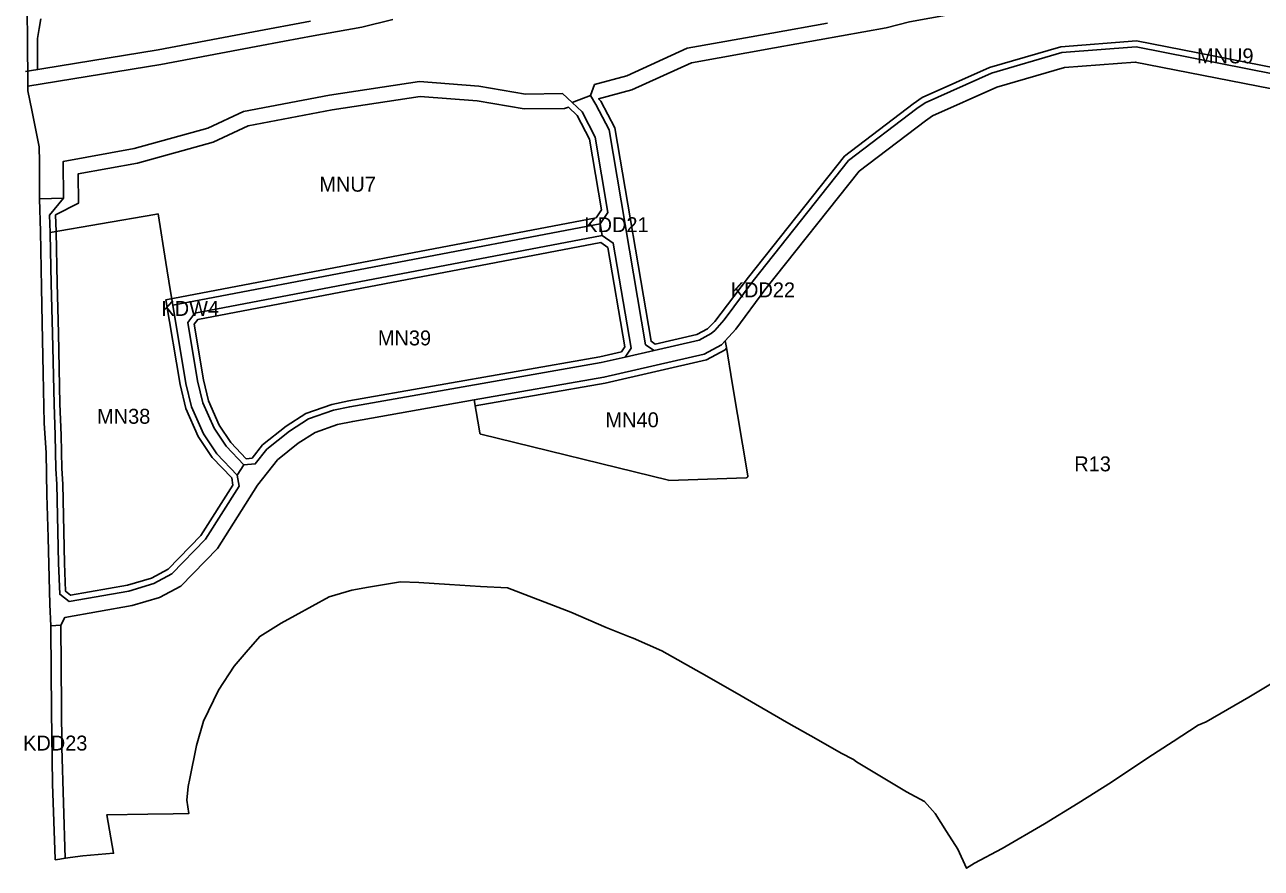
# Model space of a CAD drawing. Extents: x 7440055 to 7442242, y 5549003 to 5552256.
# Drawn here: x 7440576 to 7441405, y 5549003 to 5549569 of the extents above; entities that cross this region are included whole.
import ezdxf

# ---------------------------------------------------------------- set-up
doc = ezdxf.new("R2010")
doc.units = 0
for name, color, linetype in [('linie_rozgraniczajace', 7, 'Continuous'), ('linie_zabudowy_nieprzekraczalne', 7, 'Continuous'), ('oznaczenia_przeznaczen', 7, 'Continuous')]:
    doc.layers.add(name, color=color, linetype=linetype)

msp = doc.modelspace()

# ---------------------------------------------------------------- linework, layer by layer
at = {"layer": 'linie_rozgraniczajace'}
for points in [[(7440823.23, 5549572.15), (7440802.48, 5549567), (7440786.12, 5549564.03), (7440769.77, 5549561.06), (7440750.65, 5549557.49), (7440731.53, 5549553.91), (7440667.61, 5549541.98), (7440578.55, 5549527.43), (7440578.2, 5549559.87), (7440577.85, 5549593.22)], [(7440578.58, 5549524.38), (7440578.55, 5549527.43), (7440667.61, 5549541.98), (7440731.53, 5549553.91), (7440750.65, 5549557.49), (7440769.77, 5549561.06), (7440786.12, 5549564.03), (7440802.48, 5549567), (7440823.23, 5549572.15)], [(7441114.4, 5549569.57), (7441077.17, 5549562.92), (7441020.41, 5549552.79), (7440979.92, 5549534.41), (7440958.38, 5549528.46), (7440955.75, 5549521.17), (7440943.39, 5549516.35), (7440936.84, 5549522.52), (7440912.04, 5549522.13), (7440880.89, 5549527.4), (7440841.05, 5549530.47), (7440780.78, 5549521.32), (7440723.17, 5549510.39), (7440699.18, 5549499.3), (7440649.84, 5549485.56), (7440602.3, 5549477.01), (7440602.41, 5549452.42), (7440586.41, 5549451.77), (7440586.41, 5549452.15), (7440586.23, 5549476.79), (7440586.16, 5549486.75), (7440581.21, 5549511.31), (7440578.58, 5549524.38)], [(7441414.05, 5549535.54), (7441321.31, 5549553.68), (7441271.56, 5549549.88), (7441224.51, 5549536.13), (7441179.99, 5549516.21), (7441174.35, 5549512.4), (7441128.65, 5549477.58), (7441064.64, 5549396.93), (7441045.31, 5549370.83), (7441038.88, 5549363.69), (7441036.62, 5549361.59), (7441028.38, 5549357.15), (7440998.31, 5549350.27), (7440992.6, 5549354.08), (7440968.05, 5549498.13), (7440959.27, 5549515.02), (7440955.75, 5549521.17), (7440958.38, 5549528.46), (7440979.92, 5549534.41), (7441020.41, 5549552.79), (7441077.17, 5549562.92), (7441114.4, 5549569.57)], [(7440593.91, 5549165.7), (7440593.36, 5549179.81), (7440592.06, 5549224.79), (7440591.7, 5549239.14), (7440591.33, 5549253.49), (7440591.06, 5549267.54), (7440590.78, 5549281.6), (7440589.56, 5549301.44), (7440588.89, 5549335.09), (7440588.23, 5549368.74), (7440587.71, 5549392.53), (7440586.9, 5549430), (7440586.41, 5549451.77), (7440602.41, 5549452.42), (7440593.08, 5549441.02), (7440593.45, 5549429.24), (7440593.47, 5549428.4), (7440594.19, 5549395.2), (7440595.06, 5549361.81), (7440596.06, 5549314.32), (7440596.91, 5549293.42), (7440597.35, 5549270.93), (7440598, 5549260.51), (7440599.16, 5549207.58), (7440599.88, 5549186.82), (7440606.11, 5549181.86), (7440646.21, 5549188.94), (7440662.94, 5549193.9), (7440674.98, 5549200.38), (7440697.67, 5549223.68), (7440720.11, 5549259.17), (7440718.91, 5549266.62), (7440723.24, 5549273.46), (7440730.91, 5549274.17), (7440738.73, 5549284.11), (7440753.99, 5549296.19), (7440766.6, 5549304.29), (7440783.3, 5549310.15), (7440794.33, 5549312.51), (7440962.71, 5549342.13), (7440978.8, 5549345.81), (7440998.31, 5549350.27), (7441028.38, 5549357.15), (7441036.62, 5549361.59), (7441038.88, 5549363.69), (7441045.31, 5549370.83), (7441064.64, 5549396.93), (7441128.65, 5549477.58), (7441174.35, 5549512.4), (7441179.99, 5549516.21), (7441224.51, 5549536.13), (7441271.56, 5549549.88), (7441321.31, 5549553.68), (7441414.05, 5549535.54)], [(7440603.54, 5549009.75), (7440601.38, 5549083.97), (7440600.53, 5549165.95), (7440603.41, 5549171.23), (7440648.5, 5549179.19), (7440666.77, 5549184.6), (7440681.07, 5549192.3), (7440705.56, 5549217.46), (7440718.99, 5549238.69), (7440732.42, 5549259.91), (7440745.86, 5549277.01), (7440759.81, 5549288.04), (7440771.02, 5549295.24), (7440786.01, 5549300.51), (7440796.24, 5549302.69), (7440877.73, 5549317.03), (7440881.43, 5549294.9), (7440881.44, 5549294.84), (7440881.46, 5549294.78), (7440881.48, 5549294.72), (7440881.5, 5549294.66), (7440881.53, 5549294.6), (7440881.56, 5549294.55), (7440881.59, 5549294.5), (7440881.63, 5549294.44), (7440881.67, 5549294.4), (7440881.72, 5549294.35), (7440881.76, 5549294.31), (7440881.81, 5549294.27), (7440881.86, 5549294.23), (7440881.92, 5549294.2), (7440881.97, 5549294.17), (7440882.03, 5549294.14), (7440882.09, 5549294.12), (7440882.15, 5549294.1), (7440882.18, 5549294.1), (7441007.96, 5549263.17), (7441008.02, 5549263.16), (7441008.08, 5549263.15), (7441008.14, 5549263.15), (7441008.21, 5549263.15), (7441008.23, 5549263.15), (7441060.08, 5549264.92), (7441060.14, 5549264.92), (7441060.2, 5549264.93), (7441060.27, 5549264.94), (7441060.33, 5549264.96), (7441060.39, 5549264.98), (7441060.45, 5549265), (7441060.5, 5549265.03), (7441060.56, 5549265.06), (7441060.61, 5549265.09), (7441060.66, 5549265.13), (7441060.71, 5549265.17), (7441060.76, 5549265.22), (7441060.8, 5549265.26), (7441060.84, 5549265.31), (7441060.88, 5549265.36), (7441060.91, 5549265.42), (7441060.94, 5549265.47), (7441060.97, 5549265.53), (7441060.99, 5549265.59), (7441061.01, 5549265.65), (7441061.02, 5549265.71), (7441061.03, 5549265.77), (7441061.04, 5549265.84), (7441061.04, 5549265.9), (7441061.04, 5549265.96), (7441061.04, 5549266.02), (7441061.03, 5549266.08), (7441050.67, 5549328.58), (7441046.74, 5549352.29), (7441046.01, 5549356.67), (7441053.06, 5549364.49), (7441072.57, 5549390.85), (7441135.7, 5549470.38), (7441180.19, 5549504.27), (7441184.87, 5549507.44), (7441227.98, 5549526.72), (7441273.36, 5549539.99), (7441320.72, 5549543.6), (7441411.29, 5549525.89)], [(7441411.29, 5549525.89), (7441320.72, 5549543.6), (7441273.36, 5549539.99), (7441227.98, 5549526.72), (7441184.87, 5549507.44), (7441180.19, 5549504.27), (7441135.7, 5549470.38), (7441072.57, 5549390.85), (7441053.06, 5549364.49), (7441046.01, 5549356.67), (7441043.43, 5549353.9), (7441031.93, 5549347.7), (7440964.69, 5549332.32), (7440877.73, 5549317.03), (7440796.24, 5549302.69), (7440786.01, 5549300.51), (7440771.02, 5549295.24), (7440759.81, 5549288.04), (7440745.86, 5549277.01), (7440732.42, 5549259.91), (7440718.99, 5549238.69), (7440705.56, 5549217.46), (7440681.07, 5549192.3), (7440666.77, 5549184.6), (7440648.5, 5549179.19), (7440603.41, 5549171.23)], [(7440966.2, 5549164.55), (7440942.43, 5549174.75), (7440899.99, 5549191.07), (7440881.94, 5549192.02), (7440861.22, 5549193.3), (7440840.5, 5549194.59), (7440828.26, 5549195.02), (7440806.96, 5549191.62), (7440795.74, 5549189.49), (7440780.52, 5549185.1), (7440757.75, 5549172.48), (7440748.36, 5549167.43), (7440733.98, 5549158.49), (7440724.9, 5549147.91), (7440716.86, 5549138.54), (7440706.22, 5549122.47), (7440696.18, 5549101.65), (7440691.59, 5549085.4), (7440687.12, 5549063.29), (7440685.99, 5549057.83), (7440685.12, 5549048.67), (7440686.34, 5549039.72), (7440675.84, 5549039.58), (7440659.01, 5549039.36), (7440631.57, 5549039), (7440636.03, 5549013.17), (7440615.28, 5549011.38), (7440603.54, 5549009.75)], [(7440603.41, 5549171.23), (7440600.53, 5549165.95), (7440593.91, 5549165.7)], [(7441424.45, 5549134.26), (7441396.95, 5549117.87), (7441368.31, 5549101.16), (7441363.01, 5549099.01), (7441346.08, 5549088.12), (7441329.15, 5549077.22), (7441304.81, 5549060.8), (7441282.6, 5549046.8), (7441259.95, 5549032.95), (7441231.66, 5549016.33), (7441213.11, 5549006.49), (7441207.73, 5549003.08), (7441201.94, 5549015.9), (7441194.27, 5549027.84), (7441186.6, 5549039.78), (7441179.56, 5549047.79), (7441167.51, 5549054.39), (7441134.02, 5549074.36), (7441131.82, 5549076.1), (7441123.61, 5549080.33), (7441106.91, 5549089.91), (7441088.61, 5549100.12), (7441052.45, 5549121.05), (7441030.11, 5549133.93), (7441003.5, 5549148.84), (7440984.2, 5549157.37), (7440981.79, 5549158.34), (7440966.2, 5549164.55)]]:
    msp.add_lwpolyline(points, dxfattribs=at)
for points in [[(7440593.45, 5549429.24), (7440593.08, 5549441.02), (7440602.41, 5549452.42), (7440602.3, 5549477.01), (7440649.84, 5549485.56), (7440699.18, 5549499.3), (7440723.17, 5549510.39), (7440780.78, 5549521.32), (7440841.05, 5549530.47), (7440880.89, 5549527.4), (7440912.04, 5549522.13), (7440936.84, 5549522.52), (7440943.39, 5549516.35), (7440949.95, 5549510.18), (7440958.73, 5549493.28), (7440967.33, 5549442.8), (7440962.1, 5549435.18), (7440675.74, 5549380.5), (7440674, 5549390.99), (7440670.95, 5549409.16), (7440665.84, 5549441.75), (7440663.63, 5549441.37), (7440627.13, 5549435.07)], [(7440943.39, 5549516.35), (7440955.75, 5549521.17), (7440959.27, 5549515.02), (7440968.05, 5549498.13), (7440992.6, 5549354.08), (7440998.31, 5549350.27), (7440978.8, 5549345.81), (7440982.83, 5549351.85), (7440970.85, 5549422.2), (7440963.54, 5549427.31), (7440962.1, 5549435.18), (7440967.33, 5549442.8), (7440958.73, 5549493.28), (7440949.95, 5549510.18)], [(7440599.88, 5549186.82), (7440599.16, 5549207.58), (7440598, 5549260.51), (7440597.35, 5549270.93), (7440596.91, 5549293.42), (7440596.06, 5549314.32), (7440595.06, 5549361.81), (7440594.19, 5549395.2), (7440593.47, 5549428.4), (7440593.45, 5549429.24), (7440627.13, 5549435.07), (7440663.63, 5549441.37), (7440665.84, 5549441.75), (7440670.95, 5549409.16), (7440674, 5549390.99), (7440675.74, 5549380.5), (7440684.43, 5549328.17), (7440688.26, 5549312.52), (7440696.29, 5549294.38), (7440705.13, 5549281.02), (7440718.91, 5549266.62), (7440720.11, 5549259.17), (7440697.67, 5549223.68), (7440674.98, 5549200.38), (7440662.94, 5549193.9), (7440646.21, 5549188.94), (7440606.11, 5549181.86)], [(7440675.74, 5549380.5), (7440962.1, 5549435.18), (7440963.54, 5549427.31), (7440690.56, 5549375.18), (7440685.78, 5549368.87), (7440692.27, 5549329.78), (7440695.87, 5549315.11), (7440703.33, 5549298.23), (7440711.41, 5549286.03), (7440723.24, 5549273.46), (7440718.91, 5549266.62), (7440705.13, 5549281.02), (7440696.29, 5549294.38), (7440688.26, 5549312.52), (7440684.43, 5549328.17)], [(7440685.78, 5549368.87), (7440690.56, 5549375.18), (7440963.54, 5549427.31), (7440970.85, 5549422.2), (7440982.83, 5549351.85), (7440978.8, 5549345.81), (7440962.71, 5549342.13), (7440794.33, 5549312.51), (7440783.3, 5549310.15), (7440766.6, 5549304.29), (7440753.99, 5549296.19), (7440738.73, 5549284.11), (7440730.91, 5549274.17), (7440723.24, 5549273.46), (7440711.41, 5549286.03), (7440703.33, 5549298.23), (7440695.87, 5549315.11), (7440692.27, 5549329.78)], [(7440877.73, 5549317.03), (7440964.69, 5549332.32), (7441031.93, 5549347.7), (7441043.43, 5549353.9), (7441046.01, 5549356.67), (7441046.74, 5549352.29), (7441050.67, 5549328.58), (7441061.03, 5549266.08), (7441061.04, 5549266.02), (7441061.04, 5549265.96), (7441061.04, 5549265.9), (7441061.04, 5549265.84), (7441061.03, 5549265.77), (7441061.02, 5549265.71), (7441061.01, 5549265.65), (7441060.99, 5549265.59), (7441060.97, 5549265.53), (7441060.94, 5549265.47), (7441060.91, 5549265.42), (7441060.88, 5549265.36), (7441060.84, 5549265.31), (7441060.8, 5549265.26), (7441060.76, 5549265.22), (7441060.71, 5549265.17), (7441060.66, 5549265.13), (7441060.61, 5549265.09), (7441060.56, 5549265.06), (7441060.5, 5549265.03), (7441060.45, 5549265), (7441060.39, 5549264.98), (7441060.33, 5549264.96), (7441060.27, 5549264.94), (7441060.2, 5549264.93), (7441060.14, 5549264.92), (7441060.08, 5549264.92), (7441008.23, 5549263.15), (7441008.21, 5549263.15), (7441008.14, 5549263.15), (7441008.08, 5549263.15), (7441008.02, 5549263.16), (7441007.96, 5549263.17), (7440882.18, 5549294.1), (7440882.15, 5549294.1), (7440882.09, 5549294.12), (7440882.03, 5549294.14), (7440881.97, 5549294.17), (7440881.92, 5549294.2), (7440881.86, 5549294.23), (7440881.81, 5549294.27), (7440881.76, 5549294.31), (7440881.72, 5549294.35), (7440881.67, 5549294.4), (7440881.63, 5549294.44), (7440881.59, 5549294.5), (7440881.56, 5549294.55), (7440881.53, 5549294.6), (7440881.5, 5549294.66), (7440881.48, 5549294.72), (7440881.46, 5549294.78), (7440881.44, 5549294.84), (7440881.43, 5549294.9)], [(7440596.75, 5549008.82), (7440596.73, 5549009.27), (7440595.94, 5549034.43), (7440595.14, 5549059.59), (7440594.27, 5549108.51), (7440594.13, 5549136), (7440594, 5549163.49), (7440593.91, 5549165.7), (7440600.53, 5549165.95), (7440601.38, 5549083.97), (7440603.54, 5549009.75), (7440600.03, 5549009.27)]]:
    msp.add_lwpolyline(points, close=True, dxfattribs=at)
at = {"layer": 'linie_zabudowy_nieprzekraczalne'}
for points in [[(7441418.31, 5549616.82), (7441382.24, 5549610.65), (7441299.03, 5549597.04), (7441253.32, 5549589.77), (7441237.94, 5549583.32), (7441196.66, 5549575.44), (7441169.4, 5549570.45), (7441153.75, 5549566.44), (7441078.93, 5549553.07), (7441023.41, 5549543.16), (7440983.33, 5549524.98), (7440961.1, 5549518.84), (7440962.53, 5549517.42), (7440971.89, 5549499.42), (7440996.25, 5549356.45), (7440999.1, 5549354.55), (7441026.96, 5549360.92), (7441034.17, 5549364.81)], [(7440576.94, 5549537.3), (7440665.88, 5549551.83), (7440729.69, 5549563.74), (7440767.96, 5549570.89)], [(7440587.27, 5549572.52), (7440586.11, 5549565.96), (7440584.94, 5549559.41), (7440585, 5549543.32), (7440585.02, 5549538.62)], [(7441034.17, 5549364.81), (7441038.92, 5549369.72), (7441051.78, 5549386.3), (7441061.46, 5549399.37), (7441125.82, 5549480.45), (7441172.02, 5549515.65), (7441178.04, 5549519.72), (7441223.13, 5549539.89), (7441270.84, 5549553.84), (7441321.55, 5549557.71), (7441415.16, 5549539.4)], [(7440597.44, 5549429.79), (7440598.19, 5549395.29), (7440599.06, 5549361.9), (7440600.06, 5549314.44), (7440600.91, 5549293.54), (7440601.35, 5549271.1), (7440602, 5549260.68), (7440603.15, 5549207.7), (7440603.81, 5549188.8), (7440607.19, 5549186.12), (7440645.29, 5549192.84), (7440661.41, 5549197.61), (7440672.54, 5549203.61), (7440694.51, 5549226.17), (7440715.92, 5549260.02), (7440715.16, 5549264.75), (7440701.99, 5549278.51), (7440692.77, 5549292.45), (7440684.46, 5549311.22), (7440680.51, 5549327.36), (7440671.07, 5549384.2), (7440959.44, 5549439.25), (7440963, 5549444.44), (7440954.9, 5549491.99), (7440946.7, 5549507.75), (7440940.96, 5549513.28), (7440938.27, 5549512.54), (7440911.28, 5549512.11), (7440879.67, 5549517.47), (7440841.42, 5549520.41), (7440782.47, 5549511.46), (7440726.24, 5549500.8), (7440702.64, 5549489.89), (7440652.07, 5549475.8), (7440612.34, 5549468.65), (7440612.43, 5549448.87), (7440597.08, 5549441.08), (7440597.43, 5549429.93)], [(7440967.3, 5549419.19), (7440978.62, 5549352.75), (7440976.36, 5549349.35), (7440961.91, 5549346.05), (7440793.56, 5549316.43), (7440782.22, 5549314.01), (7440764.84, 5549307.91), (7440751.67, 5549299.45), (7440735.88, 5549286.96), (7440728.83, 5549278), (7440724.81, 5549277.62), (7440714.55, 5549288.52), (7440706.86, 5549300.16), (7440699.67, 5549316.4), (7440696.19, 5549330.58), (7440690.01, 5549367.83), (7440692.37, 5549370.95), (7440962.52, 5549422.53), (7440967.3, 5549419.19)], [(7441046.84, 5549351.69), (7441045.91, 5549350.69), (7441033.35, 5549343.92), (7440965.48, 5549328.4), (7440878.42, 5549313.09)]]:
    msp.add_lwpolyline(points, dxfattribs=at)

# ---------------------------------------------------------------- texts
at = {"layer": 'oznaczenia_przeznaczen'}
for s, p in [('MNU9', (7441362.15, 5549542.71)), ('MNU7', (7440773.9, 5549456.67)), ('KDD21', (7440951.49, 5549429.54)), ('KDD22', (7441049.62, 5549385.85)), ('KDW4', (7440668.04, 5549373.4)), ('MN39', (7440813.13, 5549353.62)), ('MN38', (7440624.94, 5549301.09)), ('MN40', (7440965.71, 5549298.74)), ('R13', (7441279.9, 5549269.2)), ('KDD23', (7440575.34, 5549082.02))]:
    msp.add_text(s, height=10, dxfattribs=at).set_placement(p)

doc.saveas('drawing.dxf')
